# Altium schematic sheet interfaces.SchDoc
size 279 x 215 mm; SheetNumber: 3; SheetTotal: 4
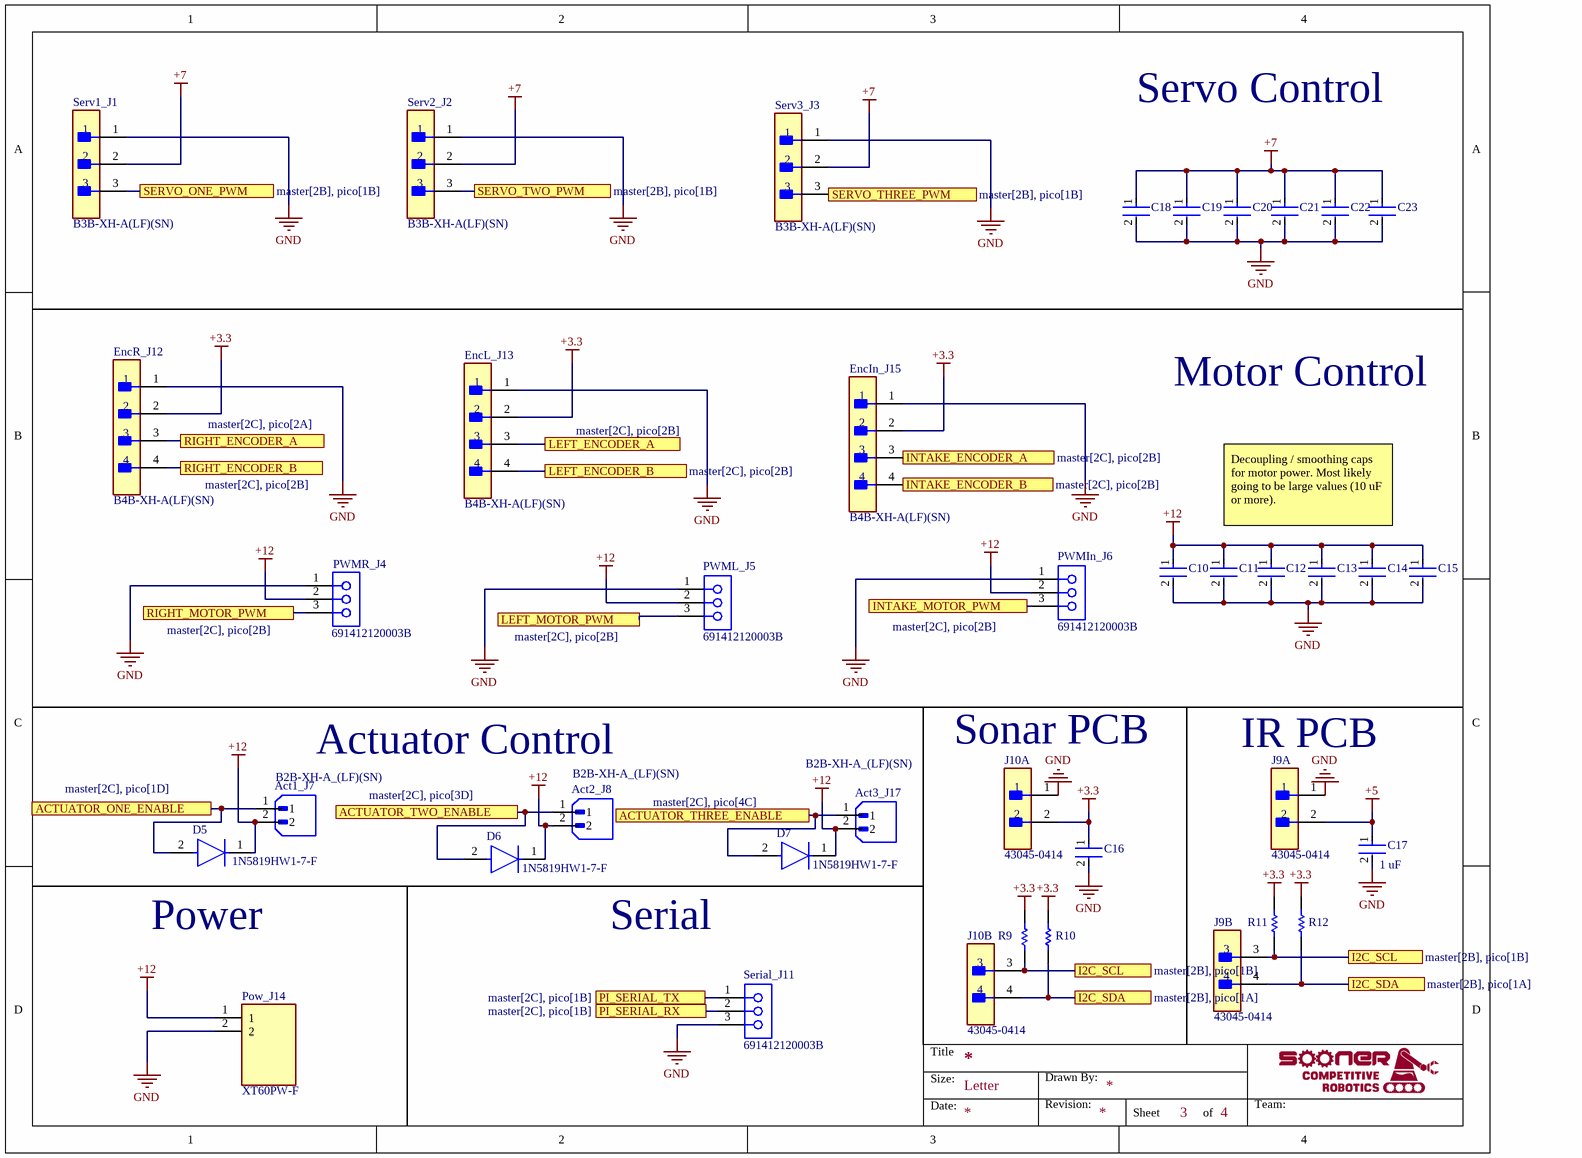
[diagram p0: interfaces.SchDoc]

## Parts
Act1_J7  B2B-XH-A_(LF)(SN)  [JST_B2B-XH-A_(LF)(SN)]
Act2_J8  B2B-XH-A_(LF)(SN)  [JST_B2B-XH-A_(LF)(SN)]
Act3_J17  B2B-XH-A_(LF)(SN)  [JST_B2B-XH-A_(LF)(SN)]
C10  GENERIC CAPACITOR  [FP-C0805C-DG-IPC_C]  (value not drawn)
C11  GENERIC CAPACITOR  [FP-C0805C-DG-IPC_C]  (value not drawn)
C12  GENERIC CAPACITOR  [FP-C0805C-DG-IPC_C]  (value not drawn)
C13  GENERIC CAPACITOR  [FP-C0805C-DG-IPC_C]  (value not drawn)
C14  GENERIC CAPACITOR  [FP-C0805C-DG-IPC_C]  (value not drawn)
C15  GENERIC CAPACITOR  [FP-C0805C-DG-IPC_C]  (value not drawn)
C16  GENERIC CAPACITOR  [FP-C0805C-DG-IPC_C]  (value not drawn)
C17  GENERIC CAPACITOR  [FP-C0805C-DG-IPC_C]  (value not drawn)
C18  GENERIC CAPACITOR  [FP-C0805C-DG-IPC_C]  (value not drawn)
C19  GENERIC CAPACITOR  [FP-C0805C-DG-IPC_C]  (value not drawn)
C20  GENERIC CAPACITOR  [FP-C0805C-DG-IPC_C]  (value not drawn)
C21  GENERIC CAPACITOR  [FP-C0805C-DG-IPC_C]  (value not drawn)
C22  GENERIC CAPACITOR  [FP-C0805C-DG-IPC_C]  (value not drawn)
C23  GENERIC CAPACITOR  [FP-C0805C-DG-IPC_C]  (value not drawn)
D5  1N5819HW1-7-F  [FP-SOD123F_Type_B-MFG]
D6  1N5819HW1-7-F  [FP-SOD123F_Type_B-MFG]
D7  1N5819HW1-7-F  [FP-SOD123F_Type_B-MFG]
EncIn_J15  B4B-XH-A(LF)(SN)  [FP-B4B-XH-A_LF_SN-MFG]
EncL_J13  B4B-XH-A(LF)(SN)  [FP-B4B-XH-A_LF_SN-MFG]
EncR_J12  B4B-XH-A(LF)(SN)  [FP-B4B-XH-A_LF_SN-MFG]
J9  43045-0414  [FP-43045-0414-MFG]  (parts A,B of 2)
J10  43045-0414  [FP-43045-0414-MFG]  (parts A,B of 2)
Pow_J14  XT60PW-F  [AMASS_XT60PW-F]
PWMIn_J6  691412120003B  [691412120003B]
PWML_J5  691412120003B  [691412120003B]
PWMR_J4  691412120003B  [691412120003B]
R9  RES 0805  [RESC2013X50X30ML20T20]  (value not drawn)
R10  RES 0805  [RESC2013X50X30ML20T20]  (value not drawn)
R11  RES 0805  [RESC2013X50X30ML20T20]  (value not drawn)
R12  RES 0805  [RESC2013X50X30ML20T20]  (value not drawn)
Serial_J11  691412120003B  [691412120003B]
Serv1_J1  B3B-XH-A(LF)(SN)  [FP-B3B-XH-A_LF_SN-MFG]
Serv2_J2  B3B-XH-A(LF)(SN)  [FP-B3B-XH-A_LF_SN-MFG]
Serv3_J3  B3B-XH-A(LF)(SN)  [FP-B3B-XH-A_LF_SN-MFG]

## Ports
ACTUATOR_ONE_ENABLE (see master[2C], pico[1D]), ACTUATOR_THREE_ENABLE (see master[2C], pico[4C]), ACTUATOR_TWO_ENABLE (see master[2C], pico[3D]), I2C_SCL (see master[2B], pico[1B]), I2C_SDA (see master[2B], pico[1A]), INTAKE_ENCODER_A (see master[2C], pico[2B]), INTAKE_ENCODER_B (see master[2C], pico[2B]), INTAKE_MOTOR_PWM (see master[2C], pico[2B]), LEFT_ENCODER_A (see master[2C], pico[2B]), LEFT_ENCODER_B (see master[2C], pico[2B]), LEFT_MOTOR_PWM (see master[2C], pico[2B]), PI_SERIAL_RX (see master[2C], pico[1B]), PI_SERIAL_TX (see master[2C], pico[1B]), RIGHT_ENCODER_A (see master[2C], pico[2A]), RIGHT_ENCODER_B (see master[2C], pico[2B]), RIGHT_MOTOR_PWM (see master[2C], pico[2B]), SERVO_ONE_PWM (see master[2B], pico[1B]), SERVO_THREE_PWM (see master[2B], pico[1B]), SERVO_TWO_PWM (see master[2B], pico[1B])

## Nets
+3.3: C16.1 EncIn_J15.2 EncL_J13.2 EncR_J12.2 J10.2 R9.2 R10.2 R11.2 R12.2
+5: C17.1 J9.2
+7: C18.1 C19.1 C20.1 C21.1 C22.1 C23.1 Serv1_J1.2 Serv2_J2.2 Serv3_J3.2
+12: Act1_J7.2 Act2_J8.2 Act3_J17.2 C10.1 C11.1 C12.1 C13.1 C14.1 C15.1 D5.1(C) D6.1(C) D7.1(C) Pow_J14.1 PWMIn_J6.2 PWML_J5.2 PWMR_J4.2
GND: C10.2 C11.2 C12.2 C13.2 C14.2 C15.2 C16.2 C17.2 C18.2 C19.2 C20.2 C21.2 C22.2 C23.2 EncIn_J15.1 EncL_J13.1 EncR_J12.1 J9.1 J10.1 Pow_J14.2 PWMIn_J6.1 PWML_J5.1 PWMR_J4.1 Serial_J11.3 Serv1_J1.1 Serv2_J2.1 Serv3_J3.1
ACTUATOR_ONE_ENABLE: Act1_J7.1 D5.2(A) ; port ACTUATOR_ONE_ENABLE
ACTUATOR_THREE_ENABLE: Act3_J17.1 D7.2(A) ; port ACTUATOR_THREE_ENABLE
ACTUATOR_TWO_ENABLE: Act2_J8.1 D6.2(A) ; port ACTUATOR_TWO_ENABLE
I2C_SCL: J9.3 J10.3 R9.1 R11.1 ; port I2C_SCL
I2C_SDA: J9.4 J10.4 R10.1 R12.1 ; port I2C_SDA
INTAKE_ENCODER_A: EncIn_J15.3 ; port INTAKE_ENCODER_A
INTAKE_ENCODER_B: EncIn_J15.4 ; port INTAKE_ENCODER_B
INTAKE_MOTOR_PWM: PWMIn_J6.3 ; port INTAKE_MOTOR_PWM
LEFT_ENCODER_A: EncL_J13.3 ; port LEFT_ENCODER_A
LEFT_ENCODER_B: EncL_J13.4 ; port LEFT_ENCODER_B
LEFT_MOTOR_PWM: PWML_J5.3 ; port LEFT_MOTOR_PWM
PI_SERIAL_RX: Serial_J11.2 ; port PI_SERIAL_RX
PI_SERIAL_TX: Serial_J11.1 ; port PI_SERIAL_TX
RIGHT_ENCODER_A: EncR_J12.3 ; port RIGHT_ENCODER_A
RIGHT_ENCODER_B: EncR_J12.4 ; port RIGHT_ENCODER_B
RIGHT_MOTOR_PWM: PWMR_J4.3 ; port RIGHT_MOTOR_PWM
SERVO_ONE_PWM: Serv1_J1.3 ; port SERVO_ONE_PWM
SERVO_THREE_PWM: Serv3_J3.3 ; port SERVO_THREE_PWM
SERVO_TWO_PWM: Serv2_J2.3 ; port SERVO_TWO_PWM

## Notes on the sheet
- Servo Control
- Motor Control
- Decoupling / smoothing caps for motor power. Most likely going to be large values (10 uF or more).
- Actuator Control
- (near J10) Sonar PCB
- (near J9) IR PCB
- (near C17) 1 uF
- (near D5) Power
- Serial

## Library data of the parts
Act1_J7 Act2_J8 Act3_J17 = CMP-002-00025-1: Connector Header Through Hole 2 position 0.098 (2.50mm); MF: JST Sales; MP: B2B-XH-A (LF)(SN)
C10-C23 = CMP-001-00083-4: GENERIC CAPACITOR 0805 or 0603(1608)
D5-D7 = CMP-12791-000028-1: DIODE SBR 40V 1A SOD123F; Manufacturer: Diodes Inc.; Max Junction Temp: +125°C; Capacitance: 30pF; Value: 30pF; Peak Reverse Current: 0.5mA; Max Surge Forward Current: 30A
EncIn_J15 EncL_J13 EncR_J12 = CMP-17439-000250-1: CONN HEADER VERT 4POS 2.5MM; Number of Contacts: 4; Contact Resistance: 20mR; Voltage Rating: 250V; Max Current Rating: 3A; Gender: Male; Wire/Cable Gauge: 22AWG; Mated Stacking Heights: 9.8mm; Insulation Resistance: 1GR
J9 J10 = CMP-04776-000520-1: CONN HEADER VERT 4POS 3MM; Approvals: UL; Current Rating: 5A; Insulation Resistance: 1GR; Max Voltage Rating (DC): 250.25kV; Gender: Male; Number of Positions: 4; Glow Wire Compliant: Compliant; Voltage Rating: 600V; Contact Resistance: 10mR; Voltage Rating (DC): 250V
Pow_J14 = CMP-002-00003-4: Socket DC Supply Connector Female; MF: AMASS
PWMIn_J6 PWML_J5 PWMR_J4 Serial_J11 = CMP-1502-02904-2: NexarPartId: 106069282
R9-R12 = CMP-009-00177-3: Surface Mount 0805 Resistor
Serv1_J1 Serv2_J2 Serv3_J3 = CMP-17439-000014-3: CONN HEADER VERT 3POS 2.5MM; Max Voltage Rating (DC): 250V; Number of Positions: 3; Current Rating: 3A; Gender: Male; Wire/Cable Gauge: 22AWG; Contact Resistance: 20mR; Insulation Resistance: 1GR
